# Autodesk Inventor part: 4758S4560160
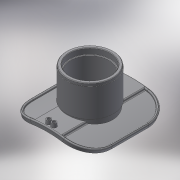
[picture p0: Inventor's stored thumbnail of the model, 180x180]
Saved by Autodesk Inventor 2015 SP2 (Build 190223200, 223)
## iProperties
Created: 2017-08
Part Number: 4758S4560160
Material: Generic
Description: PLASSON WASTEWATER SADDLE 355-560X160 SPIGOT INLET
Document SubType Name: Modeling
Designer: Кирилл
Density: 1 g/cm^3
Appearance: Default
Author: Кирилл
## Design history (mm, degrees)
derived "4758S4.ipt"
feature "Solid1::4758S4.ipt"
feature "Solid2::4758S4.ipt"
feature "Solid3::4758S4.ipt"
tag "TaggingFeature1"
body "Solid1"
other parameters: "d1" = 263, "d2" = 582.4, "d4" = 0, "d5" = 78.9, "d6" = 6.4, "d7" = 20 deg, "d8" = 10 deg, "d10" = 0, "d11" = 364, "d38" = 2.8, "d40" = 306, "d41" = 15, "d42" = 130.5, "d43" = 17.6, "d44" = 8.8, "d46" = 5 deg, "d47" = 4, "d49" = 4, "d51" = 14, "d52" = 0, "d53" = 3, "d54" = 0, "d75" = 0, "d77" = 0, "d78" = 1.6, "d82" = 125, "d84" = 156.8, "d85" = 128, "d86" = 136, "d87" = 18.75, "d88" = 152, "d89" = 18.75, "d90" = 9.375, "d91" = 1.6, "B_" = 263, "H_" = 125
